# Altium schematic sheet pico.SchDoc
size 279 x 215 mm; SheetNumber: 2; SheetTotal: 4
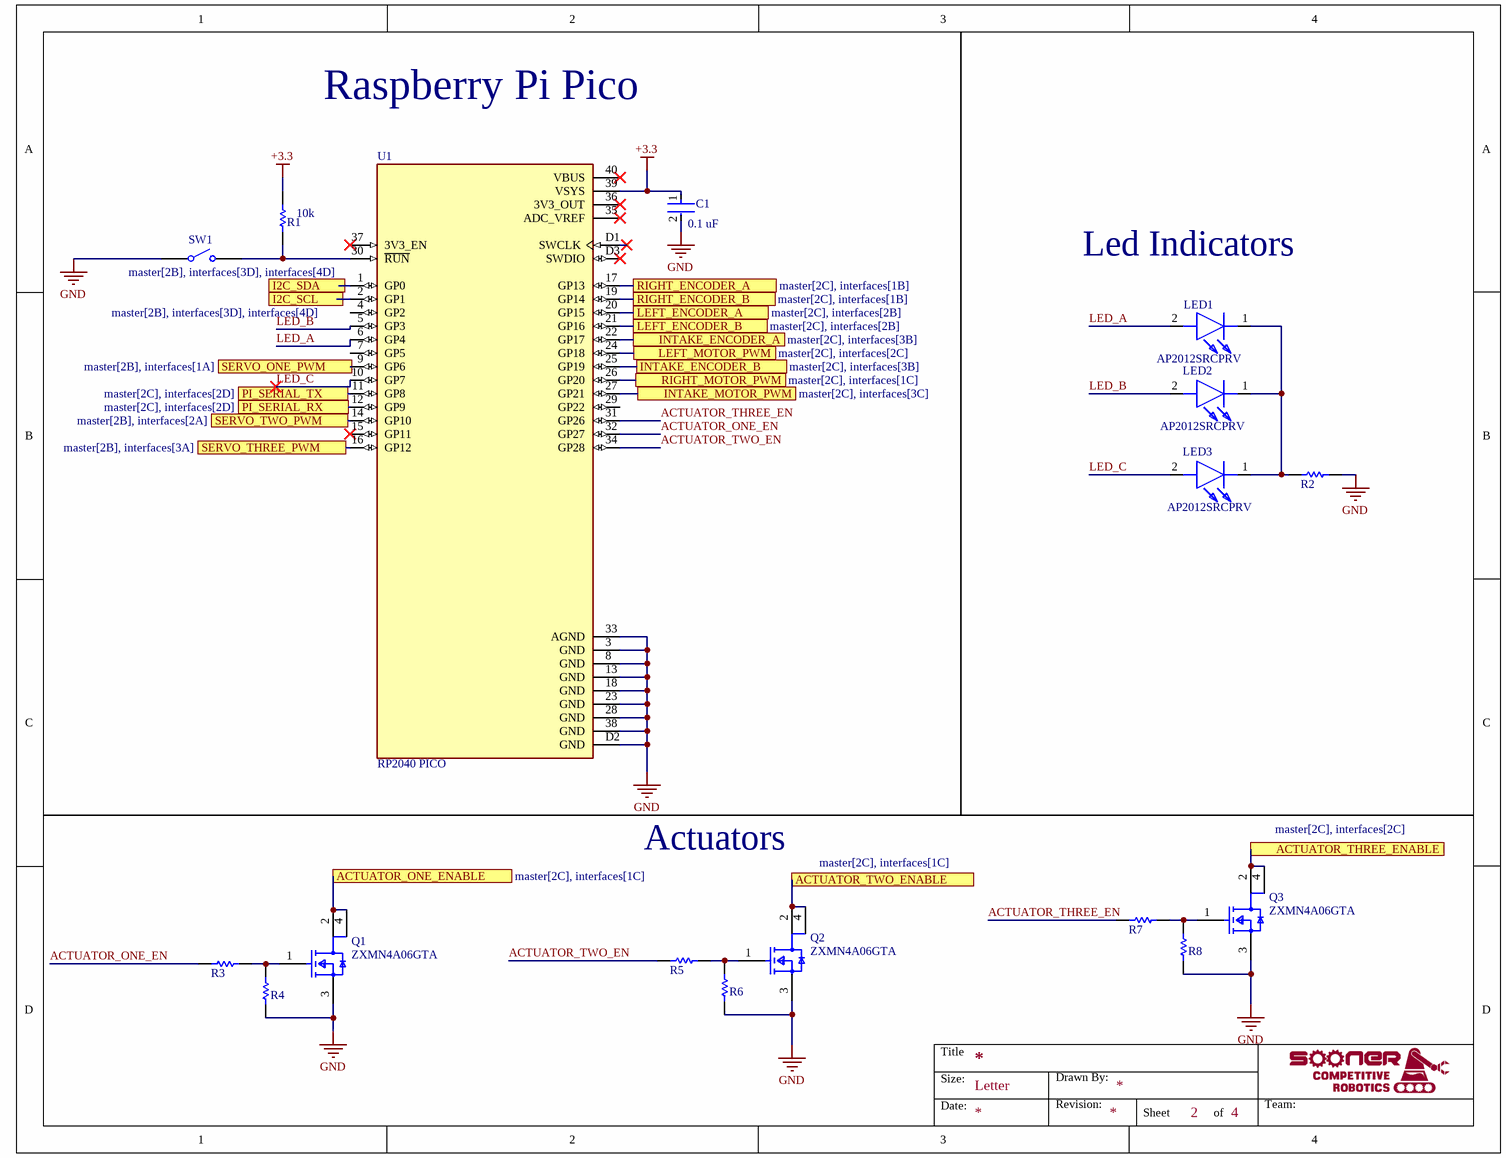
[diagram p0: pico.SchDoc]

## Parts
C1  GENERIC CAPACITOR  [FP-C0805C-DG-IPC_C]  (value not drawn)
LED1  AP2012SRCPRV  [LEDC2012X110N]
LED2  AP2012SRCPRV  [LEDC2012X110N]
LED3  AP2012SRCPRV  [LEDC2012X110N]
Q1  ZXMN4A06GTA  [FP-SOT223-IPC_C]
Q2  ZXMN4A06GTA  [FP-SOT223-IPC_C]
Q3  ZXMN4A06GTA  [FP-SOT223-IPC_C]
R1  RES 0805  [RESC2013X50X30ML20T20]  (value not drawn)
R2  RES 0805  [RESC2013X50X30ML20T20]  (value not drawn)
R3  RES 0805  [RESC2013X50X30ML20T20]  (value not drawn)
R4  RES 0805  [RESC2013X50X30ML20T20]  (value not drawn)
R5  RES 0805  [RESC2013X50X30ML20T20]  (value not drawn)
R6  RES 0805  [RESC2013X50X30ML20T20]  (value not drawn)
R7  RES 0805  [RESC2013X50X30ML20T20]  (value not drawn)
R8  RES 0805  [RESC2013X50X30ML20T20]  (value not drawn)
SW1  (no value)  [434111050826]
U1  RP2040 PICO  [RP2040 Pico footprint w/ pins]

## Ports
ACTUATOR_ONE_ENABLE (see master[2C], interfaces[1C]), ACTUATOR_THREE_ENABLE (see master[2C], interfaces[2C]), ACTUATOR_TWO_ENABLE (see master[2C], interfaces[1C]), I2C_SCL (see master[2B], interfaces[3D], interfaces[4D]), I2C_SDA (see master[2B], interfaces[3D], interfaces[4D]), INTAKE_ENCODER_A (see master[2C], interfaces[3B]), INTAKE_ENCODER_B (see master[2C], interfaces[3B]), INTAKE_MOTOR_PWM (see master[2C], interfaces[3C]), LEFT_ENCODER_A (see master[2C], interfaces[2B]), LEFT_ENCODER_B (see master[2C], interfaces[2B]), LEFT_MOTOR_PWM (see master[2C], interfaces[2C]), PI_SERIAL_RX (see master[2C], interfaces[2D]), PI_SERIAL_TX (see master[2C], interfaces[2D]), RIGHT_ENCODER_A (see master[2C], interfaces[1B]), RIGHT_ENCODER_B (see master[2C], interfaces[1B]), RIGHT_MOTOR_PWM (see master[2C], interfaces[1C]), SERVO_ONE_PWM (see master[2B], interfaces[1A]), SERVO_THREE_PWM (see master[2B], interfaces[3A]), SERVO_TWO_PWM (see master[2B], interfaces[2A])

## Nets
+3.3: C1.1 R1.2 U1.39(VSYS)
GND: C1.2 Q1.3(S) Q2.3(S) Q3.3(S) R2.2 R4.1 R6.1 R8.1 SW1.1 U1.3(GND) U1.8(GND) U1.13(GND) U1.18(GND) U1.23(GND) U1.28(GND) U1.33(AGND) U1.38(GND) U1.D2(GND)
ACTUATOR_ONE_EN: R3.1 U1.32(GP27)
ACTUATOR_ONE_ENABLE: Q1.2(D) Q1.4(D) ; port ACTUATOR_ONE_ENABLE
ACTUATOR_THREE_EN: R7.1 U1.31(GP26)
ACTUATOR_THREE_ENABLE: Q3.2(D) Q3.4(D) ; port ACTUATOR_THREE_ENABLE
ACTUATOR_TWO_EN: R5.1 U1.34(GP28)
ACTUATOR_TWO_ENABLE: Q2.2(D) Q2.4(D) ; port ACTUATOR_TWO_ENABLE
I2C_SCL: U1.2(GP1) ; port I2C_SCL
I2C_SDA: U1.1(GP0) ; port I2C_SDA
INTAKE_ENCODER_A: U1.22(GP17) ; port INTAKE_ENCODER_A
INTAKE_ENCODER_B: U1.25(GP19) ; port INTAKE_ENCODER_B
INTAKE_MOTOR_PWM: U1.27(GP21) ; port INTAKE_MOTOR_PWM
LED_A: LED1.2(A) U1.6(GP4)
LED_B: LED2.2(A) U1.5(GP3)
LED_C: LED3.2(A) U1.10(GP7)
LEFT_ENCODER_A: U1.20(GP15) ; port LEFT_ENCODER_A
LEFT_ENCODER_B: U1.21(GP16) ; port LEFT_ENCODER_B
LEFT_MOTOR_PWM: U1.24(GP18) ; port LEFT_MOTOR_PWM
PI_SERIAL_RX: U1.12(GP9) ; port PI_SERIAL_RX
PI_SERIAL_TX: U1.11(GP8) ; port PI_SERIAL_TX
RIGHT_ENCODER_A: U1.17(GP13) ; port RIGHT_ENCODER_A
RIGHT_ENCODER_B: U1.19(GP14) ; port RIGHT_ENCODER_B
RIGHT_MOTOR_PWM: U1.26(GP20) ; port RIGHT_MOTOR_PWM
SERVO_ONE_PWM: U1.9(GP6) ; port SERVO_ONE_PWM
SERVO_THREE_PWM: U1.16(GP12) ; port SERVO_THREE_PWM
SERVO_TWO_PWM: U1.14(GP10) ; port SERVO_TWO_PWM
NetLED1_1: LED1.1(K) LED2.1(K) LED3.1(K) R2.1
NetQ1_1: Q1.1(G) R3.2 R4.2
NetQ2_1: Q2.1(G) R5.2 R6.2
NetQ3_1: Q3.1(G) R7.2 R8.2
NetR1_1: R1.1 SW1.2 U1.30(~{RUN})

Not connected (* = marked no-connect by the designer): U1 4(GP2) 7(GP5) 15(GP11)* 29(GP22) 35(ADC_VREF)* 36(3V3_OUT)* 37(3V3_EN)* 40(VBUS)* D1(SWCLK)* D3(SWDIO)*

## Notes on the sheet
- Raspberry Pi Pico
- (near R1) 10k
- (near C1) 0.1 uF
- Led Indicators
- Actuators

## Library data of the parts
C1 = CMP-001-00083-4: GENERIC CAPACITOR 0805 or 0603(1608)
LED1-LED3 = CMP-013-000000-2: RED LED; Manufacturer_Name: Kingbright
Q1-Q3 = CMP-016-00004-2: Power Field-Effect Transistor, 5A I(D), 40V, 0.05ohm, 1-Element, N-Channel, Silicon, Metal-oxide Semiconductor FET
R1-R8 = CMP-009-00177-3: Surface Mount 0805 Resistor
SW1 = CMP-011-00013-1: Switch Tactile Button Spst-no 0.05A 12V
U1 = CMP-027-000000-14: RP2040 Raspberry Pi Pico - ARM Cortex-M0+ MCU 32-Bit Embedded Evaluation Board; MP: SC0915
